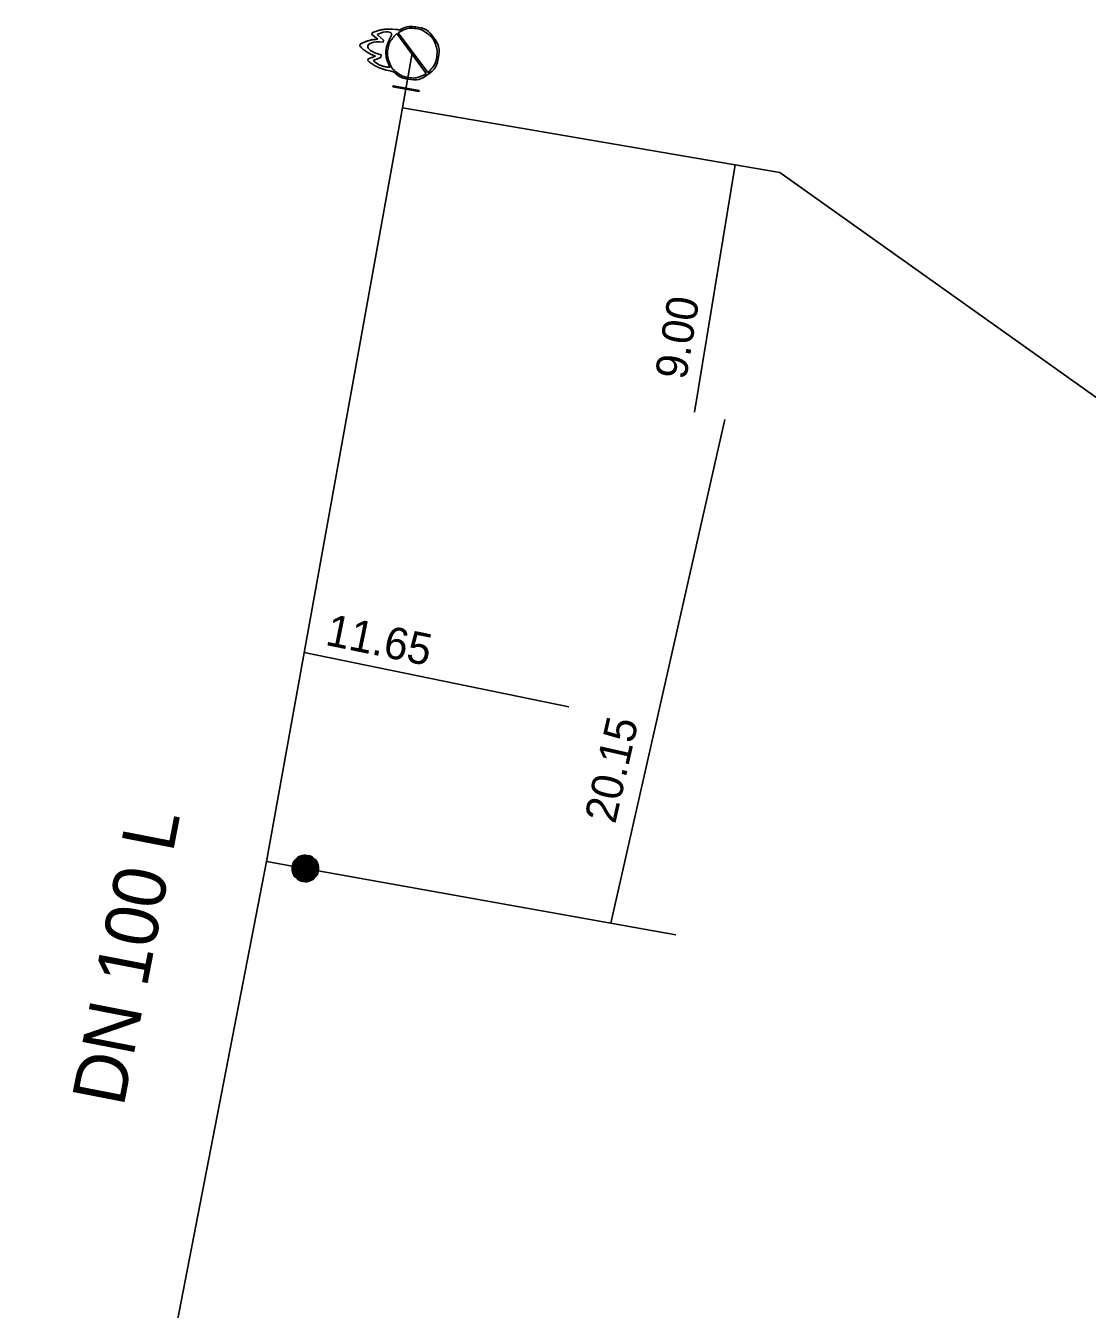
# Model space of a CAD drawing. Extents: x -820257 to -819974, y -1070894 to -1070484.
# Drawn here: x -820097.54 to -820057.29, y -1070861.03 to -1070812.37 of the extents above; entities that cross this region are included whole.
import ezdxf

# ---------------------------------------------------------------- set-up
doc = ezdxf.new("R2010")
doc.units = 0
for name, color, linetype in [('Hyd-odbočka', 7, 'Continuous'), ('Hyd-šoupě', 7, 'Continuous'), ('Hydrant', 7, 'Continuous'), ('Oměrka vodovodu', 7, 'Continuous'), ('Oměrka-text', 7, 'Continuous'), ('Přípojka vodovodu', 7, 'Continuous'), ('Přípojkový uzávěr', 7, 'Continuous'), ('Roz-řad', 7, 'Continuous'), ('Roz-řad-popis základní', 7, 'Continuous')]:
    doc.layers.add(name, color=color, linetype=linetype)

msp = doc.modelspace()

# ---------------------------------------------------------------- linework, layer by layer
at = {"layer": 'Hyd-odbočka'}
msp.add_line((-820083.25, -1070815.478), (-820082.883, -1070813.409), dxfattribs=at)
at = {"layer": 'Hyd-šoupě'}
msp.add_lwpolyline([(-820083.612, -1070814.654), (-820082.627, -1070814.829), (-820082.632, -1070814.859), (-820083.617, -1070814.685), (-820083.612, -1070814.654)], dxfattribs=at)
at = {"layer": 'Hydrant'}
for points in [[(-820084.184, -1070812.882), (-820084.414, -1070812.709), (-820084.403, -1070812.635)], [(-820084.217, -1070812.701), (-820083.979, -1070812.915), (-820083.99, -1070812.988)], [(-820083.837, -1070812.502), (-820083.632, -1070812.501), (-820083.509, -1070812.512)], [(-820082.35, -1070814.183), (-820083.464, -1070812.671)], [(-820083.415, -1070812.635), (-820082.299, -1070814.147)], [(-820084.866, -1070813.148), (-820084.854, -1070813.069)], [(-820083.881, -1070813.35), (-820083.854, -1070813.169)], [(-820084.564, -1070813.695), (-820084.553, -1070813.624), (-820084.279, -1070813.523)], [(-820084.065, -1070813.479), (-820084.079, -1070813.571), (-820084.367, -1070813.69)], [(-820083.871, -1070814.051), (-820084.065, -1070813.99)], [(-820083.601, -1070814.108), (-820083.577, -1070814.143)]]:
    msp.add_lwpolyline(points, dxfattribs=at)
for points, degree in [([(-820084.403, -1070812.635), (-820084.114, -1070812.511), (-820083.837, -1070812.502)], 2), ([(-820083.854, -1070813.169), (-820083.788, -1070812.894), (-820083.526, -1070812.65), (-820083.852, -1070812.543), (-820084.217, -1070812.701)], 3), ([(-820083.464, -1070812.671), (-820083.552, -1070812.741), (-820083.621, -1070812.831), (-820083.774, -1070813.035), (-820083.809, -1070813.268), (-820083.845, -1070813.502), (-820083.759, -1070813.742), (-820083.673, -1070813.982), (-820083.47, -1070814.141), (-820083.266, -1070814.299), (-820083.023, -1070814.336), (-820082.782, -1070814.372), (-820082.543, -1070814.282), (-820082.438, -1070814.245), (-820082.35, -1070814.183)], 3), ([(-820083.357, -1070812.527), (-820083.071, -1070812.369), (-820082.731, -1070812.42), (-820082.321, -1070812.482), (-820082.077, -1070812.816), (-820081.832, -1070813.149), (-820081.894, -1070813.561), (-820081.956, -1070813.968), (-820082.288, -1070814.214), (-820082.621, -1070814.46), (-820083.03, -1070814.398), (-820083.374, -1070814.346), (-820083.601, -1070814.108)], 3), ([(-820083.509, -1070812.512), (-820083.486, -1070812.513), (-820083.357, -1070812.527)], 2), ([(-820082.299, -1070814.147), (-820082.216, -1070814.081), (-820082.149, -1070813.992), (-820081.992, -1070813.791), (-820081.956, -1070813.549), (-820081.919, -1070813.308), (-820082.008, -1070813.068), (-820082.097, -1070812.829), (-820082.299, -1070812.674), (-820082.501, -1070812.519), (-820082.742, -1070812.482), (-820082.985, -1070812.445), (-820083.227, -1070812.537), (-820083.329, -1070812.577), (-820083.415, -1070812.635)], 3), ([(-820084.279, -1070813.523), (-820084.642, -1070813.393), (-820084.866, -1070813.148)], 2), ([(-820084.854, -1070813.069), (-820084.57, -1070812.9), (-820084.184, -1070812.882)], 2), ([(-820083.99, -1070812.988), (-820084.381, -1070812.957), (-820084.732, -1070813.127), (-820084.438, -1070813.365), (-820084.065, -1070813.479)], 3), ([(-820084.367, -1070813.69), (-820084.085, -1070813.95), (-820083.724, -1070813.941)], 2), ([(-820083.724, -1070813.941), (-820083.902, -1070813.632), (-820083.881, -1070813.35)], 2), ([(-820084.065, -1070813.99), (-820084.324, -1070813.902), (-820084.564, -1070813.695)], 2), ([(-820083.577, -1070814.143), (-820083.592, -1070814.125), (-820083.607, -1070814.107), (-820083.764, -1070814.075), (-820083.871, -1070814.051)], 3)]:
    msp.add_open_spline(points, degree=degree, dxfattribs=at)
at = {"layer": 'Oměrka vodovodu'}
for p, q in [((-820072.186, -1070827.016), (-820070.635, -1070817.648)), ((-820075.358, -1070846.388), (-820071.034, -1070827.303)), ((-820086.984, -1070836.136), (-820076.951, -1070838.195))]:
    msp.add_line(p, q, dxfattribs=at)
at = {"layer": 'Přípojka vodovodu'}
msp.add_lwpolyline([(-820088.414, -1070844.049), (-820086.938, -1070844.313), (-820072.885, -1070846.831)], dxfattribs=at)
at = {"layer": 'Přípojkový uzávěr'}
for points in [[(-820086.85, -1070843.821), (-820086.726, -1070843.843), (-820086.62, -1070843.928), (-820086.513, -1070844.012), (-820086.468, -1070844.142), (-820086.423, -1070844.273), (-820086.446, -1070844.402), (-820086.468, -1070844.53), (-820086.554, -1070844.635), (-820086.64, -1070844.74), (-820086.769, -1070844.784), (-820086.898, -1070844.828), (-820087.026, -1070844.805), (-820087.154, -1070844.782), (-820087.259, -1070844.696), (-820087.365, -1070844.61), (-820087.409, -1070844.482), (-820087.453, -1070844.353), (-820087.43, -1070844.225), (-820087.407, -1070844.097), (-820087.32, -1070843.99), (-820087.232, -1070843.883), (-820087.103, -1070843.841), (-820086.974, -1070843.798), (-820086.85, -1070843.821)], [(-820086.858, -1070843.867), (-820086.971, -1070843.847), (-820087.088, -1070843.885), (-820087.205, -1070843.923), (-820087.284, -1070844.02), (-820087.363, -1070844.117), (-820087.384, -1070844.234), (-820087.405, -1070844.349), (-820087.365, -1070844.466), (-820087.325, -1070844.582), (-820087.229, -1070844.66), (-820087.133, -1070844.738), (-820087.018, -1070844.759), (-820086.902, -1070844.78), (-820086.785, -1070844.74), (-820086.668, -1070844.7), (-820086.59, -1070844.605), (-820086.512, -1070844.509), (-820086.492, -1070844.393), (-820086.471, -1070844.277), (-820086.512, -1070844.158), (-820086.553, -1070844.04), (-820086.65, -1070843.964), (-820086.746, -1070843.887), (-820086.858, -1070843.867)], [(-820086.864, -1070843.901), (-820086.76, -1070843.919), (-820086.671, -1070843.99), (-820086.582, -1070844.061), (-820086.544, -1070844.17), (-820086.506, -1070844.279), (-820086.525, -1070844.387), (-820086.545, -1070844.495), (-820086.616, -1070844.583), (-820086.688, -1070844.671), (-820086.796, -1070844.708), (-820086.904, -1070844.745), (-820087.012, -1070844.725), (-820087.119, -1070844.706), (-820087.208, -1070844.634), (-820087.296, -1070844.562), (-820087.333, -1070844.455), (-820087.369, -1070844.347), (-820087.35, -1070844.24), (-820087.331, -1070844.131), (-820087.258, -1070844.042), (-820087.185, -1070843.953), (-820087.076, -1070843.917), (-820086.968, -1070843.882), (-820086.864, -1070843.901)], [(-820086.873, -1070843.944), (-820087.026, -1070843.916), (-820087.153, -1070844.005), (-820087.279, -1070844.094), (-820087.307, -1070844.247), (-820087.334, -1070844.4), (-820087.245, -1070844.527), (-820087.157, -1070844.655), (-820087.005, -1070844.682), (-820086.851, -1070844.71), (-820086.723, -1070844.621), (-820086.596, -1070844.532), (-820086.569, -1070844.38), (-820086.541, -1070844.226), (-820086.629, -1070844.099), (-820086.717, -1070843.972), (-820086.873, -1070843.944)], [(-820086.881, -1070843.989), (-820086.746, -1070844.013), (-820086.668, -1070844.124), (-820086.591, -1070844.236), (-820086.615, -1070844.37), (-820086.639, -1070844.504), (-820086.751, -1070844.581), (-820086.862, -1070844.659), (-820086.996, -1070844.635), (-820087.131, -1070844.611), (-820087.208, -1070844.499), (-820087.285, -1070844.388), (-820087.261, -1070844.254), (-820087.237, -1070844.12), (-820087.126, -1070844.042), (-820087.015, -1070843.965), (-820086.881, -1070843.989)], [(-820086.888, -1070844.028), (-820087.006, -1070844.007), (-820087.104, -1070844.075), (-820087.201, -1070844.143), (-820087.223, -1070844.261), (-820087.244, -1070844.379), (-820087.176, -1070844.477), (-820087.108, -1070844.575), (-820086.989, -1070844.596), (-820086.872, -1070844.617), (-820086.774, -1070844.549), (-820086.675, -1070844.481), (-820086.654, -1070844.363), (-820086.633, -1070844.245), (-820086.701, -1070844.147), (-820086.769, -1070844.049), (-820086.888, -1070844.028)], [(-820086.894, -1070844.067), (-820086.791, -1070844.085), (-820086.732, -1070844.17), (-820086.673, -1070844.255), (-820086.692, -1070844.358), (-820086.71, -1070844.459), (-820086.795, -1070844.518), (-820086.88, -1070844.577), (-820086.982, -1070844.559), (-820087.084, -1070844.541), (-820087.143, -1070844.456), (-820087.202, -1070844.371), (-820087.184, -1070844.269), (-820087.165, -1070844.167), (-820087.081, -1070844.108), (-820086.997, -1070844.048), (-820086.894, -1070844.067)], [(-820086.902, -1070844.112), (-820086.985, -1070844.098), (-820087.054, -1070844.146), (-820087.123, -1070844.193), (-820087.138, -1070844.277), (-820087.153, -1070844.36), (-820087.105, -1070844.429), (-820087.057, -1070844.497), (-820086.974, -1070844.512), (-820086.891, -1070844.527), (-820086.822, -1070844.479), (-820086.753, -1070844.431), (-820086.738, -1070844.348), (-820086.723, -1070844.265), (-820086.771, -1070844.196), (-820086.819, -1070844.127), (-820086.902, -1070844.112)], [(-820086.908, -1070844.147), (-820086.839, -1070844.159), (-820086.799, -1070844.216), (-820086.76, -1070844.273), (-820086.772, -1070844.342), (-820086.785, -1070844.411), (-820086.842, -1070844.451), (-820086.899, -1070844.491), (-820086.968, -1070844.478), (-820087.037, -1070844.466), (-820087.077, -1070844.409), (-820087.116, -1070844.352), (-820087.104, -1070844.283), (-820087.091, -1070844.214), (-820087.035, -1070844.174), (-820086.978, -1070844.134), (-820086.908, -1070844.147)], [(-820086.916, -1070844.19), (-820086.967, -1070844.181), (-820087.009, -1070844.21), (-820087.052, -1070844.24), (-820087.061, -1070844.291), (-820087.07, -1070844.342), (-820087.04, -1070844.384), (-820087.011, -1070844.427), (-820086.96, -1070844.436), (-820086.909, -1070844.445), (-820086.866, -1070844.416), (-820086.824, -1070844.386), (-820086.815, -1070844.335), (-820086.805, -1070844.284), (-820086.835, -1070844.242), (-820086.864, -1070844.199), (-820086.916, -1070844.19)], [(-820086.924, -1070844.236), (-820086.892, -1070844.242), (-820086.874, -1070844.268), (-820086.855, -1070844.294), (-820086.861, -1070844.327), (-820086.867, -1070844.358), (-820086.893, -1070844.377), (-820086.919, -1070844.396), (-820086.952, -1070844.39), (-820086.984, -1070844.384), (-820087.002, -1070844.358), (-820087.021, -1070844.331), (-820087.015, -1070844.299), (-820087.009, -1070844.266), (-820086.983, -1070844.248), (-820086.956, -1070844.23), (-820086.924, -1070844.236)], [(-820086.93, -1070844.267), (-820086.949, -1070844.263), (-820086.965, -1070844.274), (-820086.981, -1070844.285), (-820086.984, -1070844.305), (-820086.988, -1070844.324), (-820086.977, -1070844.34), (-820086.966, -1070844.356), (-820086.946, -1070844.359), (-820086.927, -1070844.363), (-820086.911, -1070844.352), (-820086.895, -1070844.34), (-820086.892, -1070844.321), (-820086.888, -1070844.301), (-820086.899, -1070844.286), (-820086.91, -1070844.27), (-820086.93, -1070844.267)]]:
    msp.add_open_spline(points, degree=3, dxfattribs=at)
at = {"layer": 'Roz-řad'}
for points in [[(-820083.25, -1070815.478), (-820088.414, -1070844.049), (-820094.255, -1070874.154), (-820096.732, -1070887.1), (-820097.541, -1070888.076)], [(-820009.275, -1070860.089), (-820009.863, -1070859.992), (-820044.329, -1070835.435), (-820068.948, -1070817.938), (-820083.25, -1070815.478)]]:
    msp.add_lwpolyline(points, dxfattribs=at)

# ---------------------------------------------------------------- texts
at = {"layer": 'Oměrka-text'}
for s, rotation, p in [(' 9.00', 80.5992, (-820072.577, -1070826.264)), ('11.65', 348.4026, (-820086.22, -1070835.834)), ('20.15', 77.2343, (-820075.191, -1070842.658))]:
    msp.add_text(s, height=1.2, rotation=rotation, dxfattribs=at).set_placement(p)
at = {"layer": 'Roz-řad-popis základní'}
msp.add_text('DN 100 L', height=2, rotation=79.0198, dxfattribs=at).set_placement((-820093.832, -1070853.385))

doc.saveas('drawing.dxf')
